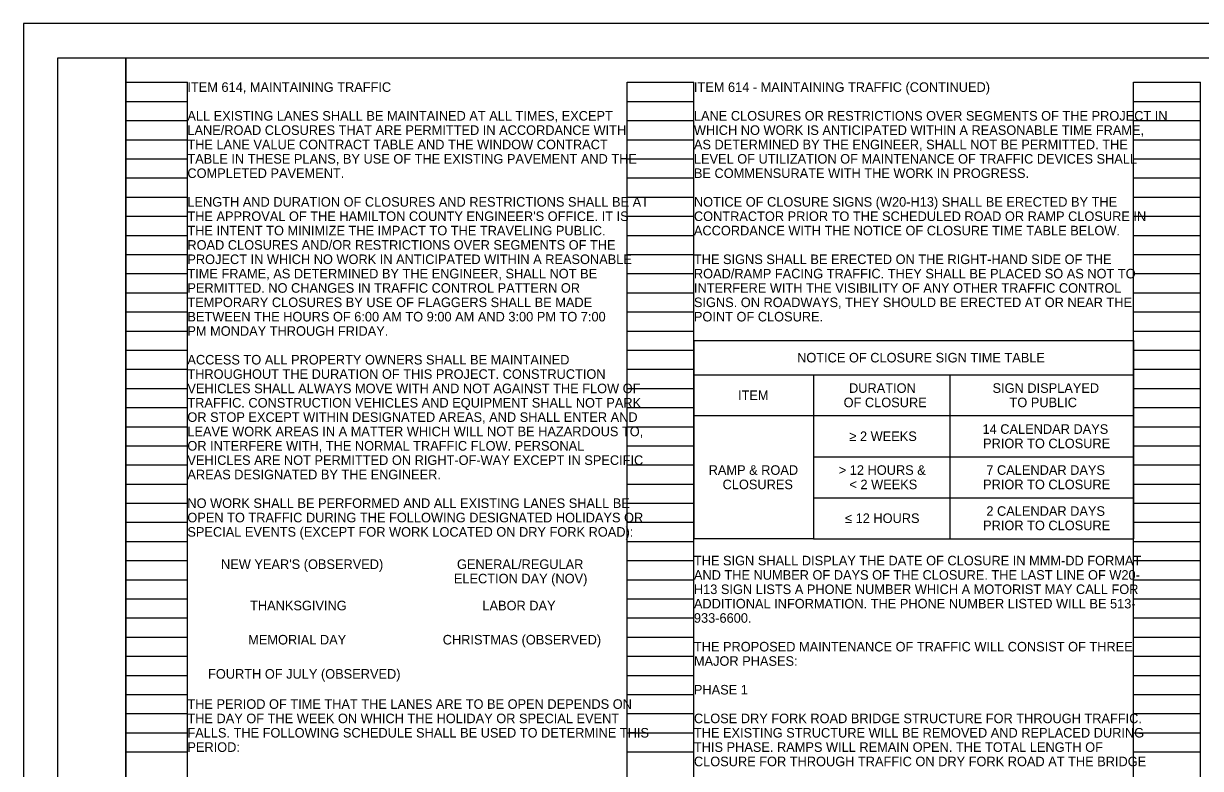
# Model space of a CAD drawing. Extents: x -65.5 to 34, y -24.3 to 23.1.
# Drawn here: x 0 to 17.24, y 11.1 to 22 of the extents above; entities that cross this region are included whole.
import ezdxf

# ---------------------------------------------------------------- set-up
doc = ezdxf.new("R2010")
doc.units = 0
for name, color, linetype in [('SH_Border', 7, 'Continuous'), ('SH_Cut_Line', 7, 'Continuous'), ('SH_Data', 7, 'Continuous'), ('SH_Text', 7, 'Continuous')]:
    doc.layers.add(name, color=color, linetype=linetype)

msp = doc.modelspace()

# ---------------------------------------------------------------- linework, layer by layer
at = {"layer": 'SH_Border'}
for points in [[(0.5, 21.5), (1.5, 21.5), (1.5, 0.5), (0.5, 0.5)], [(1.5, 21.5), (33.5, 21.5), (33.5, 0.5), (1.5, 0.5)]]:
    msp.add_lwpolyline(points, close=True, dxfattribs=at)
at = {"layer": 'SH_Cut_Line'}
msp.add_lwpolyline([(0, 0), (34, 0), (34, 22), (0, 22)], close=True, dxfattribs=at)
at = {"layer": 'SH_Data'}
for p, q in [((1.5, 0.98), (1.5, 21.14)), ((1.5, 21.14), (2.4, 21.14)), ((2.4, 0.98), (2.4, 21.14)), ((8.84, 0.98), (8.84, 21.14)), ((8.84, 21.14), (9.82, 21.14)), ((9.82, 0.98), (9.82, 21.14)), ((16.26, 0.98), (16.26, 21.14)), ((16.26, 21.14), (17.24, 21.14)), ((17.24, 0.98), (17.24, 21.14)), ((1.5, 20.86), (2.4, 20.86)), ((8.84, 20.86), (9.82, 20.86)), ((16.26, 20.86), (17.24, 20.86)), ((1.5, 20.58), (2.4, 20.58)), ((8.84, 20.58), (9.82, 20.58)), ((16.26, 20.58), (17.24, 20.58)), ((1.5, 20.3), (2.4, 20.3)), ((8.84, 20.3), (9.82, 20.3)), ((16.26, 20.3), (17.24, 20.3)), ((1.5, 20.02), (2.4, 20.02)), ((8.84, 20.02), (9.82, 20.02)), ((16.26, 20.02), (17.24, 20.02)), ((1.5, 19.74), (2.4, 19.74)), ((8.84, 19.74), (9.82, 19.74)), ((16.26, 19.74), (17.24, 19.74)), ((1.5, 19.46), (2.4, 19.46)), ((8.84, 19.46), (9.82, 19.46)), ((16.26, 19.46), (17.24, 19.46)), ((1.5, 19.18), (2.4, 19.18)), ((8.84, 19.18), (9.82, 19.18)), ((16.26, 19.18), (17.24, 19.18)), ((1.5, 18.9), (2.4, 18.9)), ((8.84, 18.9), (9.82, 18.9)), ((16.26, 18.9), (17.24, 18.9)), ((1.5, 18.62), (2.4, 18.62)), ((8.84, 18.62), (9.82, 18.62)), ((16.26, 18.62), (17.24, 18.62)), ((1.5, 18.34), (2.4, 18.34)), ((8.84, 18.34), (9.82, 18.34)), ((16.26, 18.34), (17.24, 18.34)), ((1.5, 18.06), (2.4, 18.06)), ((8.84, 18.06), (9.82, 18.06)), ((16.26, 18.06), (17.24, 18.06)), ((1.5, 17.78), (2.4, 17.78)), ((8.84, 17.78), (9.82, 17.78)), ((16.26, 17.78), (17.24, 17.78)), ((1.5, 17.5), (2.4, 17.5)), ((8.84, 17.5), (9.82, 17.5)), ((16.26, 17.5), (17.24, 17.5)), ((1.5, 17.22), (2.4, 17.22)), ((8.84, 17.22), (9.82, 17.22)), ((16.26, 17.22), (17.24, 17.22)), ((1.5, 16.94), (2.4, 16.94)), ((8.84, 16.94), (9.82, 16.94)), ((16.26, 16.94), (17.24, 16.94)), ((1.5, 16.66), (2.4, 16.66)), ((8.84, 16.66), (9.82, 16.66)), ((16.26, 16.66), (17.24, 16.66)), ((1.5, 16.38), (2.4, 16.38)), ((8.84, 16.38), (9.82, 16.38)), ((16.26, 16.38), (17.24, 16.38)), ((1.5, 16.1), (2.4, 16.1)), ((8.84, 16.1), (9.82, 16.1)), ((16.26, 16.1), (17.24, 16.1)), ((1.5, 15.82), (2.4, 15.82)), ((8.84, 15.82), (9.82, 15.82)), ((16.26, 15.82), (17.24, 15.82)), ((1.5, 15.54), (2.4, 15.54)), ((8.84, 15.54), (9.82, 15.54)), ((16.26, 15.54), (17.24, 15.54)), ((1.5, 15.26), (2.4, 15.26)), ((8.84, 15.26), (9.82, 15.26)), ((16.26, 15.26), (17.24, 15.26)), ((1.5, 14.98), (2.4, 14.98)), ((8.84, 14.98), (9.82, 14.98)), ((16.26, 14.98), (17.24, 14.98)), ((1.5, 14.7), (2.4, 14.7)), ((8.84, 14.7), (9.82, 14.7)), ((16.26, 14.7), (17.24, 14.7)), ((1.5, 14.42), (2.4, 14.42)), ((8.84, 14.42), (9.82, 14.42)), ((16.26, 14.42), (17.24, 14.42)), ((1.5, 14.14), (2.4, 14.14)), ((8.84, 14.14), (9.82, 14.14)), ((16.26, 14.14), (17.24, 14.14)), ((1.5, 13.86), (2.4, 13.86)), ((8.84, 13.86), (9.82, 13.86)), ((16.26, 13.86), (17.24, 13.86)), ((1.5, 13.58), (2.4, 13.58)), ((8.84, 13.58), (9.82, 13.58)), ((16.26, 13.58), (17.24, 13.58)), ((1.5, 13.3), (2.4, 13.3)), ((8.84, 13.3), (9.82, 13.3)), ((16.26, 13.3), (17.24, 13.3)), ((1.5, 13.02), (2.4, 13.02)), ((8.84, 13.02), (9.82, 13.02)), ((16.26, 13.02), (17.24, 13.02)), ((1.5, 12.74), (2.4, 12.74)), ((8.84, 12.74), (9.82, 12.74)), ((16.26, 12.74), (17.24, 12.74)), ((1.5, 12.46), (2.4, 12.46)), ((8.84, 12.46), (9.82, 12.46)), ((16.26, 12.46), (17.24, 12.46)), ((1.5, 12.18), (2.4, 12.18)), ((8.84, 12.18), (9.82, 12.18)), ((16.26, 12.18), (17.24, 12.18)), ((1.5, 11.9), (2.4, 11.9)), ((8.84, 11.9), (9.82, 11.9)), ((16.26, 11.9), (17.24, 11.9)), ((1.5, 11.62), (2.4, 11.62)), ((8.84, 11.62), (9.82, 11.62)), ((16.26, 11.62), (17.24, 11.62)), ((1.5, 11.34), (2.4, 11.34)), ((8.84, 11.34), (9.82, 11.34)), ((16.26, 11.34), (17.24, 11.34))]:
    msp.add_line(p, q, dxfattribs=at)
at = {"layer": 'SH_Text'}
for p, q in [((9.82, 17.36), (16.26, 17.36)), ((9.82, 17.36), (9.82, 16.86)), ((16.26, 17.36), (16.26, 16.86)), ((9.82, 16.86), (16.26, 16.86)), ((9.82, 16.86), (9.82, 16.26)), ((11.57, 16.86), (11.57, 16.26)), ((13.57, 16.86), (13.57, 16.26)), ((16.26, 16.86), (16.26, 16.26)), ((9.82, 16.26), (9.82, 14.46)), ((11.57, 16.26), (9.82, 16.26)), ((11.57, 16.26), (11.57, 14.46)), ((13.57, 16.26), (11.57, 16.26)), ((13.57, 16.26), (13.57, 15.66)), ((16.26, 16.26), (13.57, 16.26)), ((16.26, 16.26), (16.26, 15.66)), ((11.57, 15.66), (13.57, 15.66)), ((13.57, 15.66), (16.26, 15.66)), ((13.57, 15.66), (13.57, 15.06)), ((16.26, 15.66), (16.26, 15.06)), ((11.57, 15.06), (13.57, 15.06)), ((13.57, 15.06), (16.26, 15.06)), ((13.57, 15.06), (13.57, 14.46)), ((16.26, 15.06), (16.26, 14.46)), ((11.57, 14.46), (9.82, 14.46)), ((11.57, 14.46), (13.57, 14.46)), ((13.57, 14.46), (16.26, 14.46))]:
    msp.add_line(p, q, dxfattribs=at)

# ---------------------------------------------------------------- texts
for s, p in [('ITEM 614, MAINTAINING TRAFFIC', (2.4, 21)), ('ITEM 614 - MAINTAINING TRAFFIC (CONTINUED)', (9.82, 21)), ('ALL EXISTING LANES SHALL BE MAINTAINED AT ALL TIMES, EXCEPT ', (2.4, 20.58)), ('LANE CLOSURES OR RESTRICTIONS OVER SEGMENTS OF THE PROJECT IN ', (9.82, 20.58)), ('LANE/ROAD CLOSURES THAT ARE PERMITTED IN ACCORDANCE WITH ', (2.4, 20.37)), ('WHICH NO WORK IS ANTICIPATED WITHIN A REASONABLE TIME FRAME, ', (9.82, 20.37)), ('THE LANE VALUE CONTRACT TABLE AND THE WINDOW CONTRACT ', (2.4, 20.16)), ('AS DETERMINED BY THE ENGINEER, SHALL NOT BE PERMITTED. THE ', (9.82, 20.16)), ('TABLE IN THESE PLANS, BY USE OF THE EXISTING PAVEMENT AND THE ', (2.4, 19.95)), ('LEVEL OF UTILIZATION OF MAINTENANCE OF TRAFFIC DEVICES SHALL ', (9.82, 19.95)), ('COMPLETED PAVEMENT.', (2.4, 19.74)), ('BE COMMENSURATE WITH THE WORK IN PROGRESS.', (9.82, 19.74)), ('LENGTH AND DURATION OF CLOSURES AND RESTRICTIONS SHALL BE AT ', (2.4, 19.32)), ('NOTICE OF CLOSURE SIGNS (W20-H13) SHALL BE ERECTED BY THE ', (9.82, 19.32)), ("THE APPROVAL OF THE HAMILTON COUNTY ENGINEER'S OFFICE. IT IS ", (2.4, 19.11)), ('CONTRACTOR PRIOR TO THE SCHEDULED ROAD OR RAMP CLOSURE IN ', (9.82, 19.11)), ('THE INTENT TO MINIMIZE THE IMPACT TO THE TRAVELING PUBLIC. ', (2.4, 18.9)), ('ACCORDANCE WITH THE NOTICE OF CLOSURE TIME TABLE BELOW.', (9.82, 18.9)), ('ROAD CLOSURES AND/OR RESTRICTIONS OVER SEGMENTS OF THE ', (2.4, 18.69)), ('PROJECT IN WHICH NO WORK IN ANTICIPATED WITHIN A REASONABLE ', (2.4, 18.48)), ('THE SIGNS SHALL BE ERECTED ON THE RIGHT-HAND SIDE OF THE ', (9.82, 18.48)), ('TIME FRAME, AS DETERMINED BY THE ENGINEER, SHALL NOT BE ', (2.4, 18.27)), ('ROAD/RAMP FACING TRAFFIC. THEY SHALL BE PLACED SO AS NOT TO ', (9.82, 18.27)), ('PERMITTED. NO CHANGES IN TRAFFIC CONTROL PATTERN OR ', (2.4, 18.06)), ('INTERFERE WITH THE VISIBILITY OF ANY OTHER TRAFFIC CONTROL ', (9.82, 18.06)), ('TEMPORARY CLOSURES BY USE OF FLAGGERS SHALL BE MADE ', (2.4, 17.85)), ('SIGNS. ON ROADWAYS, THEY SHOULD BE ERECTED AT OR NEAR THE ', (9.82, 17.85)), ('BETWEEN THE HOURS OF 6:00 AM TO 9:00 AM AND 3:00 PM TO 7:00 ', (2.4, 17.64)), ('POINT OF CLOSURE.', (9.82, 17.64)), ('PM MONDAY THROUGH FRIDAY. ', (2.4, 17.43)), ('ACCESS TO ALL PROPERTY OWNERS SHALL BE MAINTAINED ', (2.4, 17.01)), ('NOTICE OF CLOSURE SIGN TIME TABLE', (11.332, 17.04)), ('THROUGHOUT THE DURATION OF THIS PROJECT. CONSTRUCTION ', (2.4, 16.8)), ('VEHICLES SHALL ALWAYS MOVE WITH AND NOT AGAINST THE FLOW OF ', (2.4, 16.59)), ('DURATION', (12.092, 16.595)), ('SIGN DISPLAYED', (14.195, 16.595)), ('ITEM', (10.466, 16.49)), ('TRAFFIC. CONSTRUCTION VEHICLES AND EQUIPMENT SHALL NOT PARK ', (2.4, 16.38)), ('OF CLOSURE', (12.013, 16.385)), ('TO PUBLIC', (14.443, 16.385)), ('OR STOP EXCEPT WITHIN DESIGNATED AREAS, AND SHALL ENTER AND ', (2.4, 16.17)), ('LEAVE WORK AREAS IN A MATTER WHICH WILL NOT BE HAZARDOUS TO, ', (2.4, 15.96)), ('14 CALENDAR DAYS', (14.048, 15.995)), ('OR INTERFERE WITH, THE NORMAL TRAFFIC FLOW. PERSONAL ', (2.4, 15.75)), ('≥ 2 WEEKS', (12.098, 15.89)), ('PRIOR TO CLOSURE', (14.056, 15.785)), ('VEHICLES ARE NOT PERMITTED ON RIGHT-OF-WAY EXCEPT IN SPECIFIC ', (2.4, 15.54)), ('RAMP & ROAD', (10.036, 15.395)), ('> 12 HOURS &', (11.942, 15.395)), ('7 CALENDAR DAYS', (14.104, 15.395)), ('AREAS DESIGNATED BY THE ENGINEER. ', (2.4, 15.33)), ('CLOSURES', (10.24, 15.185)), ('< 2 WEEKS', (12.098, 15.185)), ('PRIOR TO CLOSURE', (14.056, 15.185)), ('NO WORK SHALL BE PERFORMED AND ALL EXISTING LANES SHALL BE ', (2.4, 14.91)), ('OPEN TO TRAFFIC DURING THE FOLLOWING DESIGNATED HOLIDAYS OR ', (2.4, 14.7)), ('≤ 12 HOURS', (12.034, 14.69)), ('2 CALENDAR DAYS', (14.104, 14.795)), ('PRIOR TO CLOSURE', (14.056, 14.585)), ('SPECIAL EVENTS (EXCEPT FOR WORK LOCATED ON DRY FORK ROAD):', (2.4, 14.49)), ("NEW YEAR'S (OBSERVED)", (2.893, 14.017)), ('GENERAL/REGULAR', (6.349, 14.017)), ('THE SIGN SHALL DISPLAY THE DATE OF CLOSURE IN MMM-DD FORMAT ', (9.82, 14.07)), ('AND THE NUMBER OF DAYS OF THE CLOSURE. THE LAST LINE OF W20-', (9.82, 13.86)), ('ELECTION DAY (NOV)', (6.304, 13.807)), ('H13 SIGN LISTS A PHONE NUMBER WHICH A MOTORIST MAY CALL FOR ', (9.82, 13.65)), ('THANKSGIVING', (3.319, 13.412)), ('LABOR DAY', (6.722, 13.412)), ('ADDITIONAL INFORMATION. THE PHONE NUMBER LISTED WILL BE 513-', (9.82, 13.44)), ('933-6600.', (9.82, 13.23)), ('MEMORIAL DAY', (3.291, 12.912)), ('CHRISTMAS (OBSERVED)', (6.141, 12.912)), ('THE PROPOSED MAINTENANCE OF TRAFFIC WILL CONSIST OF THREE', (9.82, 12.81)), ('MAJOR PHASES:', (9.82, 12.6)), ('FOURTH OF JULY (OBSERVED)', (2.703, 12.412)), ('PHASE 1', (9.82, 12.18)), ('THE PERIOD OF TIME THAT THE LANES ARE TO BE OPEN DEPENDS ON ', (2.4, 11.97)), ('THE DAY OF THE WEEK ON WHICH THE HOLIDAY OR SPECIAL EVENT ', (2.4, 11.76)), ('CLOSE DRY FORK ROAD BRIDGE STRUCTURE FOR THROUGH TRAFFIC. ', (9.82, 11.76)), ('FALLS. THE FOLLOWING SCHEDULE SHALL BE USED TO DETERMINE THIS ', (2.4, 11.55)), ('THE EXISTING STRUCTURE WILL BE REMOVED AND REPLACED DURING ', (9.82, 11.55)), ('PERIOD:', (2.4, 11.34)), ('THIS PHASE. RAMPS WILL REMAIN OPEN. THE TOTAL LENGTH OF ', (9.82, 11.34)), ('CLOSURE FOR THROUGH TRAFFIC ON DRY FORK ROAD AT THE BRIDGE ', (9.82, 11.13))]:
    msp.add_text(s, height=0.14, dxfattribs=at).set_placement(p)

doc.saveas('drawing.dxf')
